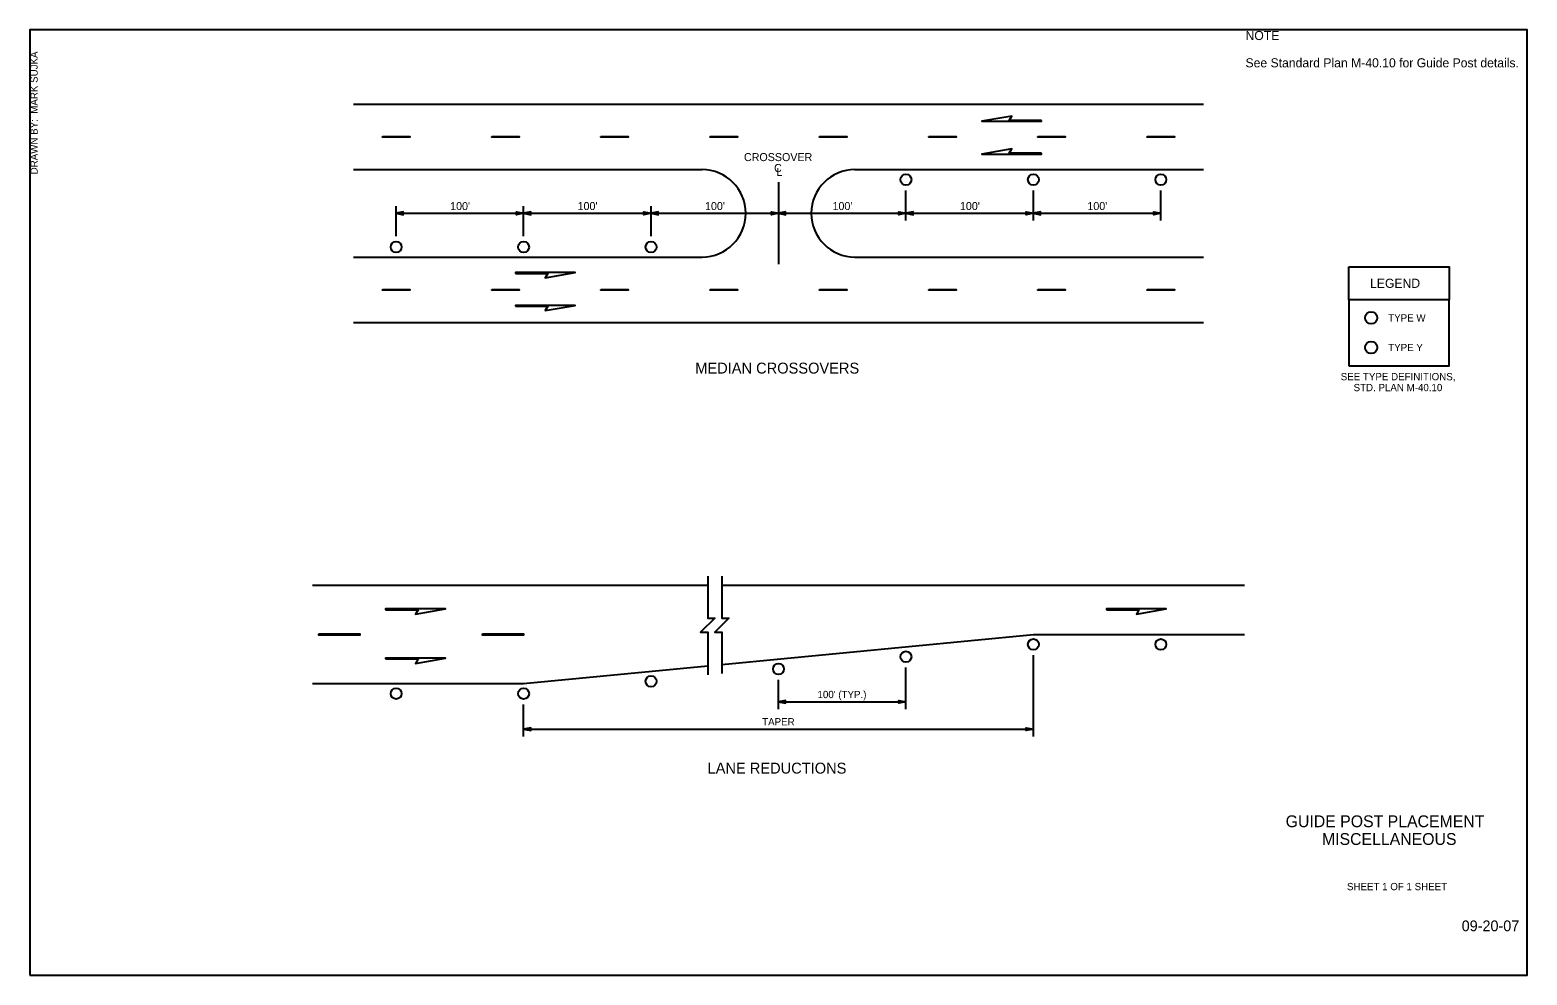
# Model space of a CAD drawing. Extents: x 99862 to 103151, y 100000 to 102076.
import ezdxf

# ---------------------------------------------------------------- set-up
doc = ezdxf.new("R2010")
doc.units = 0
for name, color, linetype in [('Level 1', 7, 'Continuous'), ('Level 15', 7, 'Continuous'), ('Level 2', 7, 'Continuous'), ('Level 20', 7, 'Continuous'), ('Level 3', 7, 'Continuous'), ('Level 40', 7, 'Continuous'), ('Level 59', 7, 'Continuous'), ('Level 60', 7, 'Continuous'), ('Level 62', 7, 'Continuous'), ('Level 7', 7, 'Continuous'), ('Level 8', 7, 'Continuous')]:
    doc.layers.add(name, color=color, linetype=linetype)

msp = doc.modelspace()

# ---------------------------------------------------------------- linework, layer by layer
at = {"layer": 'Level 1'}
msp.add_lwpolyline([(99862, 99999.5), (103151, 99999.5), (103151, 102075.5), (99862, 102075.5)], close=True, dxfattribs=at)
at = {"layer": 'Level 15'}
for p, q in [((101506.5, 101741.5), (101506.5, 101560.9)), ((101786.5, 101656.7), (101786.5, 101722.7)), ((102066.5, 101656.7), (102066.5, 101722.7)), ((102346.5, 101656.7), (102346.5, 101722.7)), ((100666.5, 101622.7), (100666.5, 101688.7)), ((100666.5, 101672.7), (100946.5, 101672.7)), ((100946.5, 101622.7), (100946.5, 101688.7)), ((100946.5, 101672.7), (101226.5, 101672.7)), ((101226.5, 101622.7), (101226.5, 101688.7)), ((101226.5, 101672.7), (101506.5, 101672.7)), ((101506.5, 101672.7), (101786.5, 101672.7)), ((101786.5, 101672.7), (102066.5, 101672.7)), ((102066.5, 101672.7), (102346.5, 101672.7)), ((102066.5, 100523.8), (102066.5, 100701.8)), ((101506.5, 100583.8), (101506.5, 100647.7)), ((101786.5, 100583.8), (101786.5, 100674.7)), ((100946.5, 100523.8), (100946.5, 100593.8)), ((101506.5, 100599.8), (101786.5, 100599.8)), ((100946.5, 100539.8), (102066.5, 100539.8))]:
    msp.add_line(p, q, dxfattribs=at)
for points in [[(100666.5, 101672.7), (100682.2, 101669.6), (100681.5, 101672.7), (100682.2, 101675.7)], [(100946.5, 101672.7), (100930.8, 101669.6), (100931.5, 101672.7), (100930.8, 101675.7)], [(100946.5, 101672.7), (100962.2, 101669.6), (100961.5, 101672.7), (100962.2, 101675.7)], [(101226.5, 101672.7), (101210.8, 101669.6), (101211.5, 101672.7), (101210.8, 101675.7)], [(101226.5, 101672.7), (101242.2, 101669.6), (101241.5, 101672.7), (101242.2, 101675.7)], [(101506.5, 101672.7), (101490.8, 101669.6), (101491.5, 101672.7), (101490.8, 101675.7)], [(101506.5, 101672.7), (101522.2, 101669.6), (101521.5, 101672.7), (101522.2, 101675.7)], [(101786.5, 101672.7), (101770.8, 101669.6), (101771.5, 101672.7), (101770.8, 101675.7)], [(101786.5, 101672.7), (101802.2, 101669.6), (101801.5, 101672.7), (101802.2, 101675.7)], [(102066.5, 101672.7), (102050.8, 101669.6), (102051.5, 101672.7), (102050.8, 101675.7)], [(102066.5, 101672.7), (102082.2, 101669.6), (102081.5, 101672.7), (102082.2, 101675.7)], [(102346.5, 101672.7), (102330.8, 101669.6), (102331.5, 101672.7), (102330.8, 101675.7)], [(101506.5, 100599.8), (101522.2, 100596.7), (101521.5, 100599.8), (101522.2, 100602.8)], [(101786.5, 100599.8), (101770.8, 100596.7), (101771.5, 100599.8), (101770.8, 100602.8)], [(100946.5, 100539.8), (100962.2, 100536.7), (100961.5, 100539.8), (100962.2, 100542.8)], [(102066.5, 100539.8), (102050.8, 100536.7), (102051.5, 100539.8), (102050.8, 100542.8)]]:
    msp.add_lwpolyline(points, close=True, dxfattribs=at)
for points in [[(101351, 100875.8), (101351, 100783.6), (101366.5, 100783.6), (101335.5, 100752.6), (101351, 100752.6), (101351, 100658.9)], [(101382, 100875.8), (101382, 100783.6), (101397.5, 100783.6), (101366.5, 100752.6), (101382, 100752.6), (101382, 100661.8)]]:
    msp.add_lwpolyline(points, dxfattribs=at)
at = {"layer": 'Level 2'}
for centre in [(101786.5, 101746.7), (102066.5, 101746.7), (102346.5, 101746.7), (100666.5, 101598.7), (100946.5, 101598.7), (101226.5, 101598.7), (101786.5, 100698.7), (102066.5, 100725.8), (102346.5, 100725.8), (101506.5, 100671.7), (101226.5, 100644.7), (100666.5, 100617.8), (100946.5, 100617.8)]:
    msp.add_circle(centre, 12, dxfattribs=at)
at = {"layer": 'Level 20'}
for centre in [(102808.6, 101443), (102808.6, 101378), (102808.6, 101378)]:
    msp.add_circle(centre, 13.4, dxfattribs=at)
at = {"layer": 'Level 3'}
for points in [[(102084.4, 101876.7), (102013.2, 101876.7), (102018.8, 101886.4), (101953.1, 101874.8), (102084.4, 101874.8)], [(102084.4, 101804.7), (102013.2, 101804.7), (102018.8, 101814.4), (101953.1, 101802.8), (102084.4, 101802.8)], [(100928.6, 101540.7), (100999.8, 101540.7), (100994.2, 101530.9), (101059.9, 101542.5), (100928.6, 101542.5)], [(100928.6, 101468.7), (100999.8, 101468.7), (100994.2, 101458.9), (101059.9, 101470.5), (100928.6, 101470.5)], [(100643.4, 100801.8), (100714.6, 100801.8), (100709, 100792.1), (100774.6, 100803.7), (100643.4, 100803.7)], [(102227.2, 100801.8), (102298.4, 100801.8), (102292.8, 100792.1), (102358.4, 100803.7), (102227.2, 100803.7)], [(100643.4, 100693.8), (100714.6, 100693.8), (100709, 100684.1), (100774.6, 100695.7), (100643.4, 100695.7)]]:
    msp.add_lwpolyline(points, close=True, dxfattribs=at)
at = {"layer": 'Level 40'}
for points in [[(102759.7, 101555), (102979.7, 101555), (102979.7, 101483), (102759.7, 101483)], [(102759.7, 101338), (102979.7, 101338), (102979.7, 101483), (102759.7, 101483)]]:
    msp.add_lwpolyline(points, close=True, dxfattribs=at)
at = {"layer": 'Level 60'}
for p, q in [((103151, 102075.5), (103151, 102075.5)), ((99862, 99999.5), (99862, 99999.5))]:
    msp.add_line(p, q, dxfattribs=at)
at = {"layer": 'Level 7'}
for points in [[(100636.5, 101841.7), (100696.5, 101841.7), (100696.5, 101839.7), (100636.5, 101839.7)], [(100876.5, 101841.7), (100936.5, 101841.7), (100936.5, 101839.7), (100876.5, 101839.7)], [(101116.5, 101841.7), (101176.5, 101841.7), (101176.5, 101839.7), (101116.5, 101839.7)], [(101356.5, 101841.7), (101416.5, 101841.7), (101416.5, 101839.7), (101356.5, 101839.7)], [(101596.5, 101841.7), (101656.5, 101841.7), (101656.5, 101839.7), (101596.5, 101839.7)], [(101836.5, 101841.7), (101896.5, 101841.7), (101896.5, 101839.7), (101836.5, 101839.7)], [(102076.5, 101841.7), (102136.5, 101841.7), (102136.5, 101839.7), (102076.5, 101839.7)], [(102316.5, 101841.7), (102376.5, 101841.7), (102376.5, 101839.7), (102316.5, 101839.7)], [(100636.5, 101505.7), (100696.5, 101505.7), (100696.5, 101503.7), (100636.5, 101503.7)], [(100876.5, 101505.7), (100936.5, 101505.7), (100936.5, 101503.7), (100876.5, 101503.7)], [(101116.5, 101505.7), (101176.5, 101505.7), (101176.5, 101503.7), (101116.5, 101503.7)], [(101356.5, 101505.7), (101416.5, 101505.7), (101416.5, 101503.7), (101356.5, 101503.7)], [(101596.5, 101505.7), (101656.5, 101505.7), (101656.5, 101503.7), (101596.5, 101503.7)], [(101836.5, 101505.7), (101896.5, 101505.7), (101896.5, 101503.7), (101836.5, 101503.7)], [(102076.5, 101505.7), (102136.5, 101505.7), (102136.5, 101503.7), (102076.5, 101503.7)], [(102316.5, 101505.7), (102376.5, 101505.7), (102376.5, 101503.7), (102316.5, 101503.7)], [(100496.5, 100749.3), (100586.5, 100749.3), (100586.5, 100746.3), (100496.5, 100746.3)], [(100856.5, 100749.3), (100946.5, 100749.3), (100946.5, 100746.3), (100856.5, 100746.3)]]:
    msp.add_lwpolyline(points, close=True, dxfattribs=at)
at = {"layer": 'Level 8'}
for p, q in [((100572.9, 101912.7), (102440.1, 101912.7)), ((100572.9, 101768.7), (101338.5, 101768.7)), ((101674.5, 101768.7), (102440.1, 101768.7)), ((100572.9, 101576.7), (101338.5, 101576.7)), ((101674.5, 101576.7), (102440.1, 101576.7)), ((100572.9, 101432.7), (102440.1, 101432.7)), ((100482.7, 100855.8), (101351, 100855.8)), ((101382, 100855.8), (102530.3, 100855.8)), ((101382, 100681.8), (102066.5, 100747.8)), ((102066.5, 100747.8), (102530.3, 100747.8)), ((100946.5, 100639.8), (101351, 100678.9)), ((100482.7, 100639.8), (100946.5, 100639.8))]:
    msp.add_line(p, q, dxfattribs=at)
for centre, start, end in [((101338.5, 101672.7), 270, 90), ((101674.5, 101672.7), 90, 270)]:
    msp.add_arc(centre, 96, start, end, dxfattribs=at)

# ---------------------------------------------------------------- texts
at = {"layer": 'Level 20'}
for s, height, p in [('NOTE', 20, (102532.5, 102053.3)), ('See Standard Plan M-40.10 for Guide Post details.', 20, (102532.5, 101993.3)), ('CROSSOVER', 17.58, (101430.6, 101787.4)), ('C', 17.6, (101496.8, 101763.4)), ('L', 17.6, (101502.2, 101754.7)), ("100'", 17.58, (100785.1, 101679.9)), ("100'", 17.58, (101065.1, 101679.9)), ("100'", 17.58, (101345.1, 101679.9)), ("100'", 17.58, (101625.1, 101679.9)), ("100'", 17.58, (101905.1, 101679.9)), ("100'", 17.58, (102185.1, 101679.9)), ('LEGEND', 20, (102806.1, 101509)), ('TYPE W', 16, (102846, 101435)), ('TYPE Y', 16, (102846, 101370)), ('MEDIAN CROSSOVERS', 24, (101323.6, 101320.7)), ('SEE TYPE DEFINITIONS,', 16, (102741.7, 101306)), ('STD. PLAN M-40.10', 16, (102769.9, 101282)), ("100' (TYP.)", 16, (101592.2, 100607.8)), ('TAPER', 16, (101470.6, 100547.8)), ('LANE REDUCTIONS', 24, (101350.7, 100442))]:
    msp.add_text(s, height=height, dxfattribs=at).set_placement(p)
at = {"layer": 'Level 59'}
msp.add_text('09-20-07', height=23.62, dxfattribs=at).set_placement((103007.4, 100095.8))
at = {"layer": 'Level 62'}
msp.add_text('DRAWN BY:  MARK SUJKA', height=16, rotation=90, dxfattribs=at).set_placement((99879, 101758.3))
for s, height, p in [('GUIDE POST PLACEMENT', 26, (102620.7, 100324.3)), ('MISCELLANEOUS', 26, (102700.4, 100285.3)), ('SHEET 1 OF 1 SHEET', 16, (102755.4, 100185.9))]:
    msp.add_text(s, height=height, dxfattribs=at).set_placement(p)

doc.saveas('drawing.dxf')
